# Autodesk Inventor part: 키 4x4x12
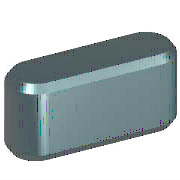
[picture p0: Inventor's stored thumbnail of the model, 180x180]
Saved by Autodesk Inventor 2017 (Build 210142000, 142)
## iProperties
Created: 2012-02
Part Number: 키 4x4x12
Material: 강철, 연강
Description: 키 및 해당 키홈
Document SubType Name: Modeling
Standard: KS B 1311
Designer: mduedu
Standards Organization: KS
Language: ko-KR
Size Designation: 4 x 4 x 12
Categories: <MemberInstance><Categories><Category DisplayName="샤프트 부품" InternalName="7f7aeb1f-a693-4053-b835-cee3144e0d98" Mnemonic="SHFT"><Category DisplayName="키" Interna
Density: 7.85 g/cm^3
Appearance: 노란색
Mass: 1.38563 g
Surface Area: 1.94869 cm^2
Volume: 0.176513 cm^3
IsCustomPart: 1
Author: mduedu
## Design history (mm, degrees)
workplane "Work Plane1"
workplane "Work Plane2"
sketch "스케치1"
  geometry: L1 (2, 2)-(10, 2); L2 (10, -2)-(2, -2); L3 (0, 9.4)-(0, -7.4) reference; L4 (-5, 0)-(30, 0) reference; L5 (12, 0)-(12, 7); A1 r 2 centre (2, 0) between (2, 2) and (2, -2); A2 r 2 centre (10, 0) between (10, -2) and (10, 2)
  constraints: 6 end point, 5 point on circle, 4 tangent, 3 point on line, 2 centre point, 1 horizontal, 1 parallel, 1 perpendicular
  dimensions: "d0" = 2 radius of A1 (= 0.5 x PB); "d13" = 2 radius of A2 (= 0.5 x PB); "d14" = 12 distance between parallel lines of L5 L3 (= NLG)
extrude "본체1" new body sketch "스케치1" taper "d3" = 0 deg; stored distance "d4" = 10
workplane "Work Plane3"
body "Solid1"
chamfer "모따기1" distance "d8" = 0.25 (= PHH); stored, may be unused: second distance "d9" = 0.25 (= PHH), angle "d15" = 45 deg
other parameters: "d1" = -2.5 (= -PNT), "d2" = 1.5 (= PH - PNT), "NLG" = 12 [user parameter; used in 3 equation terms], "PB" = 4 [user parameter; used in 2 equation terms], "PNT" = 2.5 [user parameter; used in 2 equation terms], "PH" = 4 [user parameter; used in 1 equation term], "PHH" = 0.25 [user parameter; used in 2 equation terms], "d10" = 0, "d16" = 0, "d17" = 0, "d18" = 0, "PLB2" = 12 (= NLG) [user parameter], "WDMAX" = 12 [user parameter], "PLB1" = 12 (= NLG) [user parameter], "RR" = 0.08 [user parameter], "PUEB" = 1.8 [user parameter]
